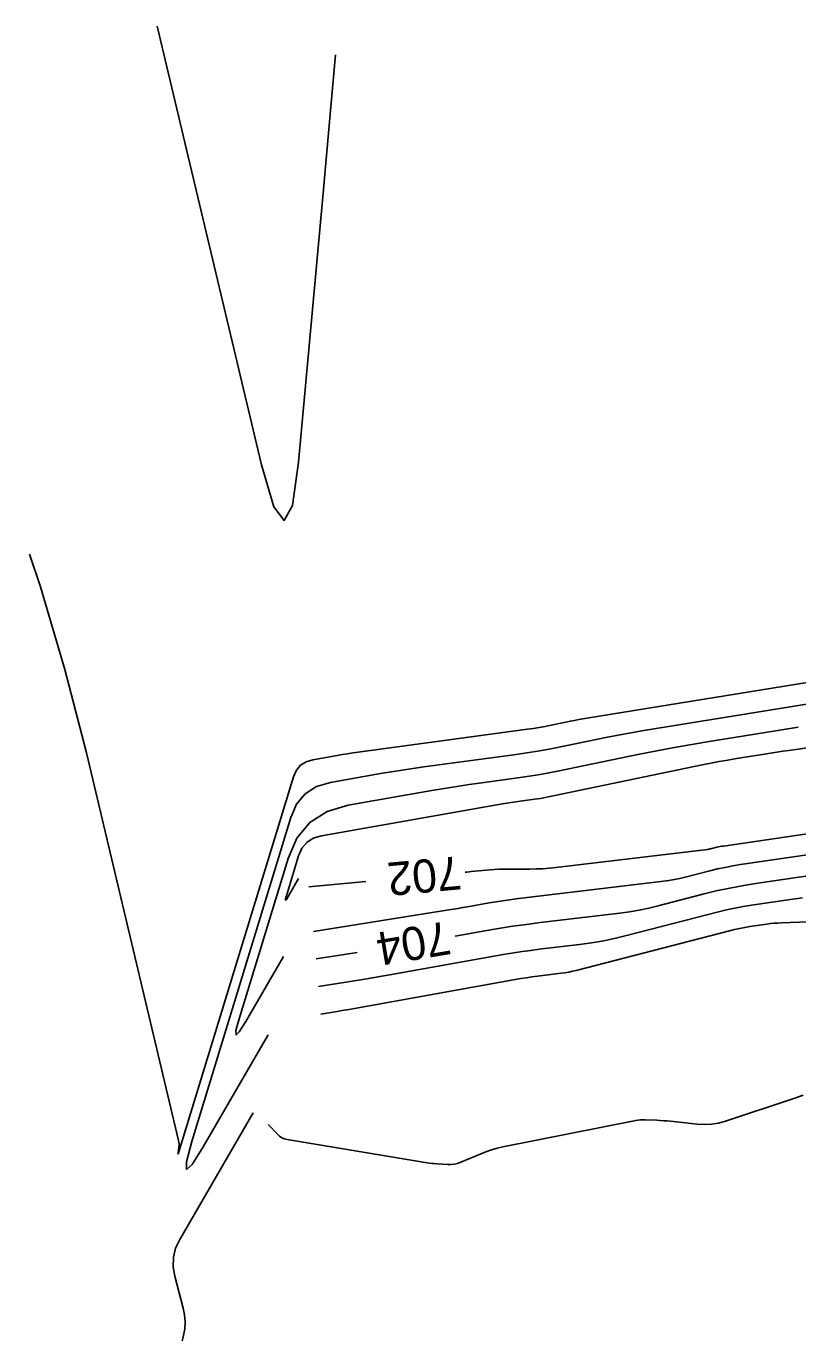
# Model space of a CAD drawing. Extents: x -468541894 to 3393103, y -306086142 to 1227927.
# Drawn here: x 1843039.2 to 1843132.3, y 539573.5 to 539731 of the extents above; entities that cross this region are included whole.
import ezdxf

# ---------------------------------------------------------------- set-up
doc = ezdxf.new("R2010")
doc.units = 0
doc.layers.add('DT_X_Contour_Minor', color=7, linetype='Continuous')
doc.layers.add('Level 19', color=7, linetype='Continuous')

msp = doc.modelspace()

# ---------------------------------------------------------------- linework, layer by layer
at = {"layer": 'DT_X_Contour_Minor'}
for points in [[(1843076.55, 539727.5), (1843075.94, 539720.78), (1843075.04, 539710.85), (1843072.1, 539678.42), (1843071.35, 539673.19), (1843070.35, 539671.39), (1843069.11, 539673.03), (1843067.61, 539678.1), (1843055.05, 539730.95)], [(1843039.66, 539667.32), (1843040.99, 539663.39), (1843043.93, 539653.46), (1843046.51, 539643.42), (1843057.62, 539596.69), (1843057.66, 539596.49), (1843057.68, 539596.29), (1843057.68, 539596.08), (1843057.66, 539595.88), (1843057.58, 539595.21), (1843057.57, 539595.1), (1843057.57, 539595.06), (1843057.59, 539595.09), (1843057.63, 539595.2), (1843071.48, 539640.52), (1843071.83, 539641.3), (1843072.33, 539641.91), (1843072.99, 539642.33), (1843073.81, 539642.58), (1843076.75, 539643.1), (1843077.38, 539643.2), (1843078.01, 539643.3), (1843078.64, 539643.4), (1843079.27, 539643.49), (1843099.69, 539646.25), (1843100.41, 539646.35), (1843101.12, 539646.47), (1843101.84, 539646.59), (1843102.55, 539646.74), (1843104.87, 539647.22), (1843105.37, 539647.32), (1843105.87, 539647.41), (1843106.37, 539647.5), (1843106.87, 539647.58), (1843141.86, 539653.23)], [(1843068.44, 539609.44), (1843060.61, 539595.95), (1843059.27, 539593.81), (1843058.59, 539593.21), (1843058.57, 539594.12), (1843059.21, 539596.56), (1843071.15, 539635.6), (1843071.86, 539637.21), (1843072.9, 539638.46), (1843074.26, 539639.33), (1843075.95, 539639.84), (1843081.99, 539640.9), (1843083.29, 539641.12), (1843084.59, 539641.33), (1843085.88, 539641.52), (1843087.19, 539641.71), (1843098.04, 539643.17), (1843099.61, 539643.4), (1843101.17, 539643.65), (1843102.73, 539643.93), (1843104.28, 539644.24), (1843109.35, 539645.29), (1843110.43, 539645.51), (1843111.52, 539645.71), (1843112.61, 539645.91), (1843113.71, 539646.09), (1843135.58, 539649.62)], [(1843070.27, 539618.85), (1843065.73, 539611.02), (1843064.95, 539609.78), (1843064.55, 539609.43), (1843064.54, 539609.96), (1843064.92, 539611.37), (1843070.82, 539630.68), (1843071.9, 539633.12), (1843073.47, 539635.01), (1843075.53, 539636.33), (1843078.09, 539637.1), (1843088.15, 539638.87), (1843089.66, 539639.12), (1843091.16, 539639.36), (1843092.67, 539639.59), (1843094.18, 539639.8), (1843099.11, 539640.47), (1843100.17, 539640.62), (1843101.22, 539640.79), (1843102.27, 539640.98), (1843103.32, 539641.19), (1843113.01, 539643.19), (1843115.09, 539643.61), (1843117.18, 539644.01), (1843119.27, 539644.38), (1843121.36, 539644.73), (1843130.38, 539646.19), (1843132.32, 539646.49)], [(1843072.1, 539628.26), (1843070.84, 539626.09), (1843070.63, 539625.75), (1843070.52, 539625.65), (1843070.52, 539625.8), (1843070.62, 539626.19), (1843072.09, 539630.99), (1843072.49, 539631.91), (1843073.09, 539632.62), (1843073.87, 539633.13), (1843074.84, 539633.42), (1843096.68, 539637.25), (1843097.21, 539637.34), (1843097.74, 539637.42), (1843098.27, 539637.5), (1843098.8, 539637.58), (1843100.54, 539637.81), (1843100.91, 539637.86), (1843101.28, 539637.92), (1843101.65, 539637.99), (1843102.02, 539638.06), (1843120.76, 539641.94), (1843121.79, 539642.15), (1843122.82, 539642.35), (1843123.86, 539642.53), (1843124.89, 539642.71), (1843128.28, 539643.25), (1843129.01, 539643.37), (1843129.74, 539643.48), (1843130.47, 539643.59), (1843131.19, 539643.7), (1843150.66, 539646.5)], [(1843148.39, 539635.85), (1843123.31, 539632.18), (1843123.11, 539632.15), (1843122.92, 539632.11), (1843122.73, 539632.07), (1843122.54, 539632.02), (1843121.92, 539631.86), (1843121.78, 539631.83), (1843121.65, 539631.8), (1843121.52, 539631.78), (1843121.38, 539631.76), (1843103.11, 539629.58), (1843102.33, 539629.5), (1843101.54, 539629.44), (1843100.75, 539629.41), (1843099.96, 539629.39), (1843097.39, 539629.39), (1843096.84, 539629.39), (1843096.29, 539629.37), (1843095.73, 539629.34), (1843095.18, 539629.29), (1843092.92, 539629.09), (1843092.44, 539629.04), (1843092.17, 539629.02)], [(1843142.3, 539632.41), (1843125.38, 539629.94), (1843124.44, 539629.79), (1843123.52, 539629.61), (1843122.59, 539629.41), (1843121.68, 539629.19), (1843118.69, 539628.42), (1843118.05, 539628.26), (1843117.4, 539628.13), (1843116.75, 539628.02), (1843116.09, 539627.93), (1843098.32, 539625.81), (1843097.51, 539625.71), (1843096.7, 539625.59), (1843095.9, 539625.47), (1843095.09, 539625.33), (1843092.47, 539624.86), (1843091.91, 539624.76), (1843091.35, 539624.67), (1843090.78, 539624.57), (1843090.22, 539624.48), (1843073.9, 539621.88)], [(1843080.22, 539627.91), (1843073.34, 539627.27)], [(1843136.26, 539628.99), (1843127.45, 539627.7), (1843125.78, 539627.43), (1843124.11, 539627.11), (1843122.46, 539626.76), (1843120.82, 539626.36), (1843115.46, 539624.97), (1843114.31, 539624.69), (1843113.15, 539624.45), (1843111.98, 539624.26), (1843110.81, 539624.1), (1843101.24, 539622.96), (1843099.56, 539622.74), (1843097.88, 539622.51), (1843096.21, 539622.24), (1843094.54, 539621.96), (1843090.97, 539621.32)], [(1843132.86, 539625.92), (1843131.41, 539625.73), (1843126.7, 539625.04), (1843125.7, 539624.88), (1843124.7, 539624.69), (1843123.7, 539624.48), (1843122.71, 539624.24), (1843111.8, 539621.42), (1843110.35, 539621.07), (1843108.9, 539620.77), (1843107.43, 539620.52), (1843105.96, 539620.32), (1843101.12, 539619.74), (1843100.09, 539619.61), (1843099.06, 539619.46), (1843098.03, 539619.3), (1843097, 539619.13), (1843084.44, 539616.88), (1843083.3, 539616.68), (1843082.15, 539616.49), (1843081, 539616.3), (1843079.86, 539616.11), (1843074.49, 539615.25)], [(1843074.79, 539611.94), (1843076.73, 539612.25), (1843077.14, 539612.32), (1843077.56, 539612.39), (1843077.97, 539612.46), (1843078.38, 539612.53), (1843098.91, 539616.2), (1843099.57, 539616.31), (1843100.23, 539616.41), (1843100.89, 539616.51), (1843101.56, 539616.59), (1843103.74, 539616.85), (1843104.2, 539616.91), (1843104.67, 539616.99), (1843105.12, 539617.09), (1843105.58, 539617.2), (1843124.06, 539621.98), (1843124.67, 539622.12), (1843125.28, 539622.26), (1843125.9, 539622.37), (1843126.51, 539622.47), (1843128.54, 539622.77), (1843128.98, 539622.83), (1843129.41, 539622.87), (1843129.85, 539622.9), (1843130.29, 539622.93), (1843147.97, 539623.55)], [(1843079.14, 539619.35), (1843074.2, 539618.57)], [(1843132.94, 539602.15), (1843131.79, 539601.77), (1843123.56, 539599.02), (1843122.73, 539598.79), (1843121.88, 539598.65), (1843121.03, 539598.61), (1843120.17, 539598.65), (1843116.95, 539599.01), (1843116.54, 539599.05), (1843116.12, 539599.08), (1843115.7, 539599.11), (1843115.28, 539599.14), (1843113.9, 539599.21), (1843113.61, 539599.21), (1843113.32, 539599.2), (1843113.03, 539599.17), (1843112.74, 539599.12), (1843096.74, 539595.92), (1843096.03, 539595.76), (1843095.34, 539595.57), (1843094.66, 539595.34), (1843093.99, 539595.07), (1843091.65, 539594.08), (1843091.27, 539593.94), (1843090.88, 539593.85), (1843090.48, 539593.81), (1843090.08, 539593.81), (1843088.75, 539593.89), (1843088.46, 539593.91), (1843088.18, 539593.94), (1843087.9, 539593.98), (1843087.61, 539594.02), (1843070.72, 539596.83), (1843070.38, 539596.91), (1843070.07, 539597.04), (1843069.79, 539597.22), (1843069.54, 539597.45), (1843068.41, 539598.64)], [(1843066.6, 539600.03), (1843057.77, 539584.79), (1843057.27, 539583.72), (1843057.01, 539582.63), (1843056.97, 539581.5), (1843057.17, 539580.34), (1843058.18, 539576.5), (1843058.35, 539575.68), (1843058.41, 539574.86), (1843058.37, 539574.03), (1843058.22, 539573.21), (1843055.45, 539561.69), (1843054.91, 539559.22), (1843054.49, 539556.73), (1843054.19, 539554.22), (1843054.01, 539551.69), (1843053.59, 539542.84), (1843053.39, 539540.98), (1843052.96, 539539.18), (1843052.31, 539537.45), (1843051.44, 539535.79), (1843039.24, 539515.55)]]:
    msp.add_lwpolyline(points, dxfattribs=at)

# ---------------------------------------------------------------- texts
at = {"layer": 'Level 19'}
for s, rotation, p in [('702', 185.31, (1843091.53, 539630.97)), ('704', 189.4395, (1843090.03, 539623.15))]:
    msp.add_text(s, height=4, rotation=rotation, dxfattribs=at).set_placement(p)

doc.saveas('drawing.dxf')
